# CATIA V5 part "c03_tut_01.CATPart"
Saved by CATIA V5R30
Part number: c03tut1
Bounding box of the stored display mesh (mm): x -1 to 1, y -100 to 100, z -100 to 100
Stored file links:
  D:\PROJECTS\CATIA V56R 2020\Resources\c03_catia_v5_6r2020_tut\c03_tut_01.CATPart
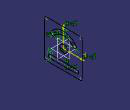
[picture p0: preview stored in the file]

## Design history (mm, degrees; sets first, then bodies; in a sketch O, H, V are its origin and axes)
Body1 (main body)
  Sketch1 on yz-plane, origin (0, 0, 0), H (0, 1, 0), V (0, 0, 1)
    line L1 (100, 90) -> (100, -90)
    line L2 (90, -100) -> (-90, -100)
    line L3 (-100, -90) -> (-100, 90)
    line L4 (-90, 100) -> (90, 100)
    arc A1 centre (90, 90) radius 10 from (100, 90) to (90, 100) ccw
    arc A2 centre (-90, 90) radius 10 from (-100, 90) to (-90, 100) cw
    arc A3 centre (90, -90) radius 10 from (100, -90) to (90, -100) cw
    arc A4 centre (-90, -90) radius 10 from (-90, -100) to (-100, -90) cw
    circle A5 centre (0, 0) radius 20
    construction line L5 (-70, -70) -> (70, -70)
    line L6 (-70, -60) -> (70, -60)
    line L7 (70, -80) -> (-70, -80)
    arc A6 centre (70, -70) radius 10 from (70, -60) to (70, -80) cw
    arc A7 centre (-70, -70) radius 10 from (-70, -80) to (-70, -60) cw
    construction arc A8 centre (0, 0) radius 70 from (57.3406, 40.1504) to (-57.3406, 40.1504) ccw
    construction line L8 (0, 0) -> (57.3406, 40.1504)
    construction line L9 (0, 0) -> (-57.3406, 40.1504)
    arc A9 centre (57.3406, 40.1504) radius 10 from (65.5322, 45.8861) to (49.1491, 34.4146) cw
    arc A10 centre (-57.3406, 40.1504) radius 10 from (-49.1491, 34.4146) to (-65.5322, 45.8861) cw
    arc A11 centre (0, 0) radius 60 from (49.1491, 34.4146) to (-49.1491, 34.4146) ccw
    arc A12 centre (0, 0) radius 80 from (-65.5322, 45.8861) to (65.5322, 45.8861) cw
    radius A1 = 10
    radius A2 = 10
    radius A3 = 10
    radius A4 = 10
    distance L5 L6 = 10
    radius A8 = 70
    angle L8 L9 = 110
    radius A10 = 10
    vertical: L1 V, L3 V
    horizontal: L2 H, L4 H, L5 H
    equidistance: L1 L3 O, L2 L4 O
    tangency: A1 L1, A1 L4, A2 L3, A2 L4, A3 L1, A3 L2, A4 L2, A4 L3, A6 L6, A7 L6, A6 L7, A7 L7, A11 A10, A10 A12, A12 A9, A9 A11
    concentricity: A11 O, A12 O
